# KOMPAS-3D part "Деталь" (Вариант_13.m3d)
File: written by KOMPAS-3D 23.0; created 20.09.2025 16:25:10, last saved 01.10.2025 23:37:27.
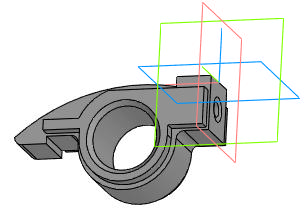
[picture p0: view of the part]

Document properties: Автор: ssafo; Полное имя файла: C:\Users\ssafo\OneDrive\Desktop\ЦД_Грант\Решенные варианты\Вариант_13.m3d

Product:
- Part/product: Деталь
    Масса: 0.301745
    Форматы листов документа: A4

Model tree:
1. Эскиз:1
2. Элемент выдавливания:1
     Расстояние 1 = 10; Расстояние 2 = 10
3. Эскиз:2  (with: Элемент выдавливания:1)
4. Элемент выдавливания:2
     Расстояние 1 = 5
5. Эскиз:3  (with: Элемент выдавливания:2)
6. Элемент выдавливания:3
     Расстояние 2 = 25
7. Фаска:1  (with: Элемент выдавливания:3)
     Угол = 45; Длина 1 = 2; Длина 2 = 2
8. Зеркальный массив:2
9. Экземпляр ( 1 )
10. Экземпляр ( 2 )  (with: Элемент выдавливания:3, Фаска:1, Элемент выдавливания:2)
11. Эскиз:4  (with: Элемент выдавливания:1)
12. Элемент выдавливания:4
     Расстояние 2 = 10
13. Фаска:2  (with: Элемент выдавливания:4)
     Угол = 15; Длина 1 = 2; Длина 2 = 0.535898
